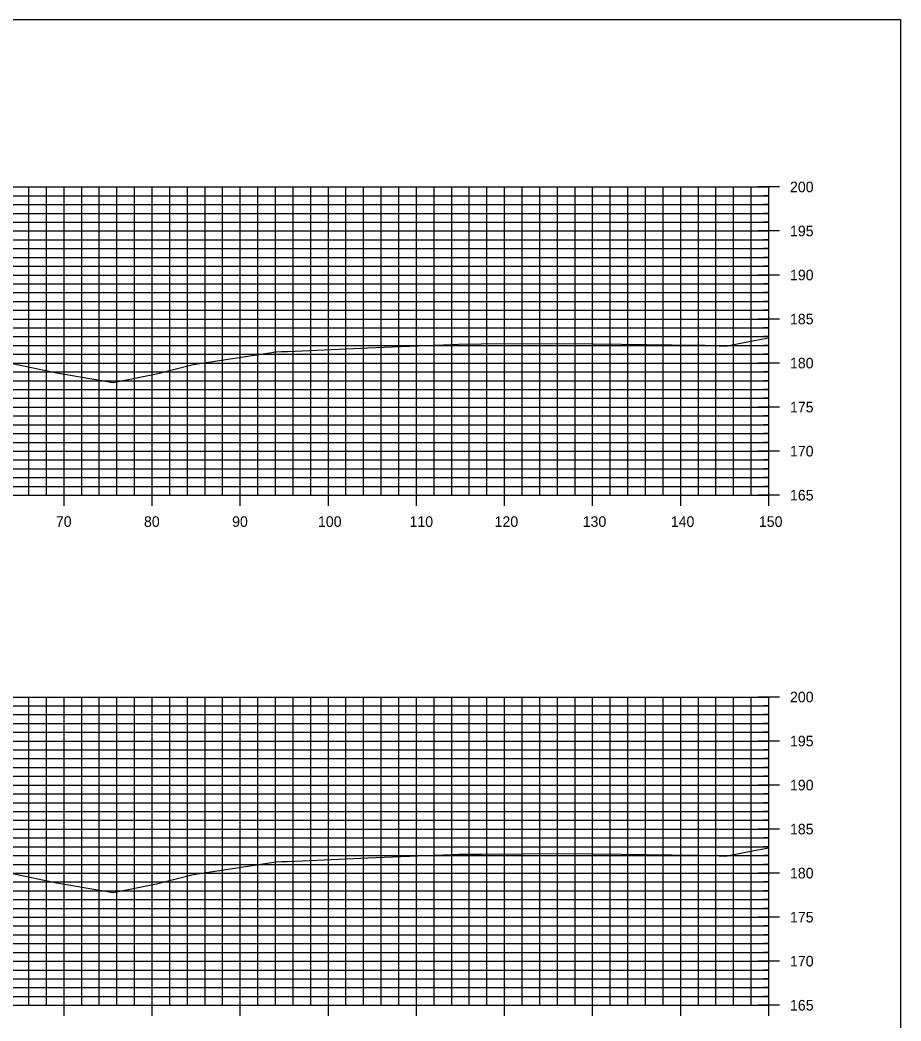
# Model space of a CAD drawing. Extents: x 1405440 to 1409538, y 1842123 to 1843178.
# Drawn here: x 1408947.6 to 1409047.6, y 1842829.8 to 1842943.5 of the extents above; entities that cross this region are included whole.
import ezdxf

# ---------------------------------------------------------------- set-up
doc = ezdxf.new("R2010")
doc.units = 0
for name, color, linetype in [('R_Axis Annot', 7, 'Continuous'), ('R_Exist Surface', 7, 'Continuous'), ('R_Grid_Minor', 7, 'Continuous'), ('R_Grid_Tick', 7, 'Continuous')]:
    doc.layers.add(name, color=color, linetype=linetype)

msp = doc.modelspace()

# ---------------------------------------------------------------- linework, layer by layer
for p, q in [((1408732.62, 1842924.51), (1409032.62, 1842924.51)), ((1408952.62, 1842889.51), (1408952.62, 1842924.51)), ((1408962.62, 1842889.51), (1408962.62, 1842924.51)), ((1408972.62, 1842889.51), (1408972.62, 1842924.51)), ((1408982.62, 1842889.51), (1408982.62, 1842924.51)), ((1408992.62, 1842889.51), (1408992.62, 1842924.51)), ((1409002.62, 1842889.51), (1409002.62, 1842924.51)), ((1409012.62, 1842889.51), (1409012.62, 1842924.51)), ((1409022.62, 1842889.51), (1409022.62, 1842924.51)), ((1409032.62, 1842889.51), (1409032.62, 1842924.51)), ((1409032.62, 1842889.51), (1409032.62, 1842924.51)), ((1408732.62, 1842919.51), (1409032.62, 1842919.51)), ((1408732.62, 1842914.51), (1409032.62, 1842914.51)), ((1408732.62, 1842909.51), (1409032.62, 1842909.51)), ((1408732.62, 1842904.51), (1409032.62, 1842904.51)), ((1408732.62, 1842899.51), (1409032.62, 1842899.51)), ((1408732.62, 1842894.51), (1409032.62, 1842894.51)), ((1408732.62, 1842889.51), (1409032.62, 1842889.51)), ((1408732.62, 1842889.51), (1409032.62, 1842889.51)), ((1408732.62, 1842866.59), (1409032.62, 1842866.59)), ((1408952.62, 1842831.59), (1408952.62, 1842866.59)), ((1408962.62, 1842831.59), (1408962.62, 1842866.59)), ((1408972.62, 1842831.59), (1408972.62, 1842866.59)), ((1408982.62, 1842831.59), (1408982.62, 1842866.59)), ((1408992.62, 1842831.59), (1408992.62, 1842866.59)), ((1409002.62, 1842831.59), (1409002.62, 1842866.59)), ((1409012.62, 1842831.59), (1409012.62, 1842866.59)), ((1409022.62, 1842831.59), (1409022.62, 1842866.59)), ((1409032.62, 1842831.59), (1409032.62, 1842866.59)), ((1409032.62, 1842831.59), (1409032.62, 1842866.59)), ((1408732.62, 1842861.59), (1409032.62, 1842861.59)), ((1408732.62, 1842856.59), (1409032.62, 1842856.59)), ((1408732.62, 1842851.59), (1409032.62, 1842851.59)), ((1408732.62, 1842846.59), (1409032.62, 1842846.59)), ((1408732.62, 1842841.59), (1409032.62, 1842841.59)), ((1408732.62, 1842836.59), (1409032.62, 1842836.59)), ((1408732.62, 1842831.59), (1409032.62, 1842831.59)), ((1408732.62, 1842831.59), (1409032.62, 1842831.59))]:
    msp.add_line(p, q)
msp.add_lwpolyline([(1408707.62, 1842723.47), (1409047.62, 1842723.47), (1409047.62, 1842943.47), (1408707.62, 1842943.47)], close=True)
at = {"layer": 'R_Exist Surface'}
for points in [[(1408942.42, 1842905.36), (1408951.8, 1842903.41), (1408958.19, 1842902.3), (1408963.11, 1842903.28), (1408967.28, 1842904.36), (1408976.7, 1842905.8), (1408977.29, 1842905.82), (1408977.99, 1842905.83), (1408987.09, 1842906.24), (1408989.9, 1842906.36), (1408996.59, 1842906.63), (1408997.4, 1842906.66), (1409000.02, 1842906.68), (1409009.47, 1842906.74), (1409015.89, 1842906.66), (1409021.63, 1842906.58), (1409022.6, 1842906.56), (1409024.57, 1842906.57), (1409026.22, 1842906.5), (1409027.7, 1842906.42), (1409030.97, 1842907.08), (1409032.62, 1842907.38)], [(1408942.42, 1842847.44), (1408951.8, 1842845.5), (1408958.19, 1842844.38), (1408963.11, 1842845.37), (1408967.28, 1842846.44), (1408976.7, 1842847.89), (1408977.29, 1842847.9), (1408977.99, 1842847.92), (1408987.09, 1842848.32), (1408989.9, 1842848.44), (1408996.59, 1842848.71), (1408997.4, 1842848.74), (1409000.02, 1842848.76), (1409009.47, 1842848.82), (1409015.89, 1842848.74), (1409021.63, 1842848.66), (1409022.6, 1842848.64), (1409024.57, 1842848.65), (1409026.22, 1842848.58), (1409027.7, 1842848.51), (1409030.97, 1842849.16), (1409032.62, 1842849.46)]]:
    msp.add_lwpolyline(points, dxfattribs=at)
at = {"layer": 'R_Grid_Minor'}
for p, q in [((1408948.62, 1842889.51), (1408948.62, 1842924.51)), ((1408950.62, 1842889.51), (1408950.62, 1842924.51)), ((1408954.62, 1842889.51), (1408954.62, 1842924.51)), ((1408956.62, 1842889.51), (1408956.62, 1842924.51)), ((1408958.62, 1842889.51), (1408958.62, 1842924.51)), ((1408960.62, 1842889.51), (1408960.62, 1842924.51)), ((1408964.62, 1842889.51), (1408964.62, 1842924.51)), ((1408966.62, 1842889.51), (1408966.62, 1842924.51)), ((1408968.62, 1842889.51), (1408968.62, 1842924.51)), ((1408970.62, 1842889.51), (1408970.62, 1842924.51)), ((1408974.62, 1842889.51), (1408974.62, 1842924.51)), ((1408976.62, 1842889.51), (1408976.62, 1842924.51)), ((1408978.62, 1842889.51), (1408978.62, 1842924.51)), ((1408980.62, 1842889.51), (1408980.62, 1842924.51)), ((1408984.62, 1842889.51), (1408984.62, 1842924.51)), ((1408986.62, 1842889.51), (1408986.62, 1842924.51)), ((1408988.62, 1842889.51), (1408988.62, 1842924.51)), ((1408990.62, 1842889.51), (1408990.62, 1842924.51)), ((1408994.62, 1842889.51), (1408994.62, 1842924.51)), ((1408996.62, 1842889.51), (1408996.62, 1842924.51)), ((1408998.62, 1842889.51), (1408998.62, 1842924.51)), ((1409000.62, 1842889.51), (1409000.62, 1842924.51)), ((1409004.62, 1842889.51), (1409004.62, 1842924.51)), ((1409006.62, 1842889.51), (1409006.62, 1842924.51)), ((1409008.62, 1842889.51), (1409008.62, 1842924.51)), ((1409010.62, 1842889.51), (1409010.62, 1842924.51)), ((1409014.62, 1842889.51), (1409014.62, 1842924.51)), ((1409016.62, 1842889.51), (1409016.62, 1842924.51)), ((1409018.62, 1842889.51), (1409018.62, 1842924.51)), ((1409020.62, 1842889.51), (1409020.62, 1842924.51)), ((1409024.62, 1842889.51), (1409024.62, 1842924.51)), ((1409026.62, 1842889.51), (1409026.62, 1842924.51)), ((1409028.62, 1842889.51), (1409028.62, 1842924.51)), ((1409030.62, 1842889.51), (1409030.62, 1842924.51)), ((1408732.62, 1842923.51), (1409032.62, 1842923.51)), ((1408732.62, 1842922.51), (1409032.62, 1842922.51)), ((1408732.62, 1842921.51), (1409032.62, 1842921.51)), ((1408732.62, 1842920.51), (1409032.62, 1842920.51)), ((1408732.62, 1842918.51), (1409032.62, 1842918.51)), ((1408732.62, 1842917.51), (1409032.62, 1842917.51)), ((1408732.62, 1842916.51), (1409032.62, 1842916.51)), ((1408732.62, 1842915.51), (1409032.62, 1842915.51)), ((1408732.62, 1842913.51), (1409032.62, 1842913.51)), ((1408732.62, 1842912.51), (1409032.62, 1842912.51)), ((1408732.62, 1842911.51), (1409032.62, 1842911.51)), ((1408732.62, 1842910.51), (1409032.62, 1842910.51)), ((1408732.62, 1842908.51), (1409032.62, 1842908.51)), ((1408732.62, 1842907.51), (1409032.62, 1842907.51)), ((1408732.62, 1842906.51), (1409032.62, 1842906.51)), ((1408732.62, 1842905.51), (1409032.62, 1842905.51)), ((1408732.62, 1842903.51), (1409032.62, 1842903.51)), ((1408732.62, 1842902.51), (1409032.62, 1842902.51)), ((1408732.62, 1842901.51), (1409032.62, 1842901.51)), ((1408732.62, 1842900.51), (1409032.62, 1842900.51)), ((1408732.62, 1842898.51), (1409032.62, 1842898.51)), ((1408732.62, 1842897.51), (1409032.62, 1842897.51)), ((1408732.62, 1842896.51), (1409032.62, 1842896.51)), ((1408732.62, 1842895.51), (1409032.62, 1842895.51)), ((1408732.62, 1842893.51), (1409032.62, 1842893.51)), ((1408732.62, 1842892.51), (1409032.62, 1842892.51)), ((1408732.62, 1842891.51), (1409032.62, 1842891.51)), ((1408732.62, 1842890.51), (1409032.62, 1842890.51)), ((1408948.62, 1842831.59), (1408948.62, 1842866.59)), ((1408950.62, 1842831.59), (1408950.62, 1842866.59)), ((1408954.62, 1842831.59), (1408954.62, 1842866.59)), ((1408956.62, 1842831.59), (1408956.62, 1842866.59)), ((1408958.62, 1842831.59), (1408958.62, 1842866.59)), ((1408960.62, 1842831.59), (1408960.62, 1842866.59)), ((1408964.62, 1842831.59), (1408964.62, 1842866.59)), ((1408966.62, 1842831.59), (1408966.62, 1842866.59)), ((1408968.62, 1842831.59), (1408968.62, 1842866.59)), ((1408970.62, 1842831.59), (1408970.62, 1842866.59)), ((1408974.62, 1842831.59), (1408974.62, 1842866.59)), ((1408976.62, 1842831.59), (1408976.62, 1842866.59)), ((1408978.62, 1842831.59), (1408978.62, 1842866.59)), ((1408980.62, 1842831.59), (1408980.62, 1842866.59)), ((1408984.62, 1842831.59), (1408984.62, 1842866.59)), ((1408986.62, 1842831.59), (1408986.62, 1842866.59)), ((1408988.62, 1842831.59), (1408988.62, 1842866.59)), ((1408990.62, 1842831.59), (1408990.62, 1842866.59)), ((1408994.62, 1842831.59), (1408994.62, 1842866.59)), ((1408996.62, 1842831.59), (1408996.62, 1842866.59)), ((1408998.62, 1842831.59), (1408998.62, 1842866.59)), ((1409000.62, 1842831.59), (1409000.62, 1842866.59)), ((1409004.62, 1842831.59), (1409004.62, 1842866.59)), ((1409006.62, 1842831.59), (1409006.62, 1842866.59)), ((1409008.62, 1842831.59), (1409008.62, 1842866.59)), ((1409010.62, 1842831.59), (1409010.62, 1842866.59)), ((1409014.62, 1842831.59), (1409014.62, 1842866.59)), ((1409016.62, 1842831.59), (1409016.62, 1842866.59)), ((1409018.62, 1842831.59), (1409018.62, 1842866.59)), ((1409020.62, 1842831.59), (1409020.62, 1842866.59)), ((1409024.62, 1842831.59), (1409024.62, 1842866.59)), ((1409026.62, 1842831.59), (1409026.62, 1842866.59)), ((1409028.62, 1842831.59), (1409028.62, 1842866.59)), ((1409030.62, 1842831.59), (1409030.62, 1842866.59)), ((1408732.62, 1842865.59), (1409032.62, 1842865.59)), ((1408732.62, 1842864.59), (1409032.62, 1842864.59)), ((1408732.62, 1842863.59), (1409032.62, 1842863.59)), ((1408732.62, 1842862.59), (1409032.62, 1842862.59)), ((1408732.62, 1842860.59), (1409032.62, 1842860.59)), ((1408732.62, 1842859.59), (1409032.62, 1842859.59)), ((1408732.62, 1842858.59), (1409032.62, 1842858.59)), ((1408732.62, 1842857.59), (1409032.62, 1842857.59)), ((1408732.62, 1842855.59), (1409032.62, 1842855.59)), ((1408732.62, 1842854.59), (1409032.62, 1842854.59)), ((1408732.62, 1842853.59), (1409032.62, 1842853.59)), ((1408732.62, 1842852.59), (1409032.62, 1842852.59)), ((1408732.62, 1842850.59), (1409032.62, 1842850.59)), ((1408732.62, 1842849.59), (1409032.62, 1842849.59)), ((1408732.62, 1842848.59), (1409032.62, 1842848.59)), ((1408732.62, 1842847.59), (1409032.62, 1842847.59)), ((1408732.62, 1842845.59), (1409032.62, 1842845.59)), ((1408732.62, 1842844.59), (1409032.62, 1842844.59)), ((1408732.62, 1842843.59), (1409032.62, 1842843.59)), ((1408732.62, 1842842.59), (1409032.62, 1842842.59)), ((1408732.62, 1842840.59), (1409032.62, 1842840.59)), ((1408732.62, 1842839.59), (1409032.62, 1842839.59)), ((1408732.62, 1842838.59), (1409032.62, 1842838.59)), ((1408732.62, 1842837.59), (1409032.62, 1842837.59)), ((1408732.62, 1842835.59), (1409032.62, 1842835.59)), ((1408732.62, 1842834.59), (1409032.62, 1842834.59)), ((1408732.62, 1842833.59), (1409032.62, 1842833.59)), ((1408732.62, 1842832.59), (1409032.62, 1842832.59))]:
    msp.add_line(p, q, dxfattribs=at)
at = {"layer": 'R_Grid_Tick'}
for p, q in [((1409033.82, 1842924.51), (1409031.42, 1842924.51)), ((1409032.62, 1842923.51), (1409032.02, 1842923.51)), ((1409032.62, 1842922.51), (1409032.02, 1842922.51)), ((1409032.62, 1842921.51), (1409032.02, 1842921.51)), ((1409032.62, 1842920.51), (1409032.02, 1842920.51)), ((1409033.82, 1842919.51), (1409031.42, 1842919.51)), ((1409032.62, 1842918.51), (1409032.02, 1842918.51)), ((1409032.62, 1842917.51), (1409032.02, 1842917.51)), ((1409032.62, 1842916.51), (1409032.02, 1842916.51)), ((1409032.62, 1842915.51), (1409032.02, 1842915.51)), ((1409033.82, 1842914.51), (1409031.42, 1842914.51)), ((1409032.62, 1842913.51), (1409032.02, 1842913.51)), ((1409032.62, 1842912.51), (1409032.02, 1842912.51)), ((1409032.62, 1842911.51), (1409032.02, 1842911.51)), ((1409032.62, 1842910.51), (1409032.02, 1842910.51)), ((1409033.82, 1842909.51), (1409031.42, 1842909.51)), ((1409032.62, 1842908.51), (1409032.02, 1842908.51)), ((1409032.62, 1842907.51), (1409032.02, 1842907.51)), ((1409032.62, 1842906.51), (1409032.02, 1842906.51)), ((1409033.82, 1842904.51), (1409031.42, 1842904.51)), ((1409032.62, 1842905.51), (1409032.02, 1842905.51)), ((1409032.62, 1842903.51), (1409032.02, 1842903.51)), ((1409032.62, 1842902.51), (1409032.02, 1842902.51)), ((1409032.62, 1842901.51), (1409032.02, 1842901.51)), ((1409032.62, 1842900.51), (1409032.02, 1842900.51)), ((1409033.82, 1842899.51), (1409031.42, 1842899.51)), ((1409032.62, 1842898.51), (1409032.02, 1842898.51)), ((1409032.62, 1842897.51), (1409032.02, 1842897.51)), ((1409032.62, 1842896.51), (1409032.02, 1842896.51)), ((1409032.62, 1842895.51), (1409032.02, 1842895.51)), ((1409033.82, 1842894.51), (1409031.42, 1842894.51)), ((1409032.62, 1842893.51), (1409032.02, 1842893.51)), ((1409032.62, 1842892.51), (1409032.02, 1842892.51)), ((1409032.62, 1842891.51), (1409032.02, 1842891.51)), ((1408948.62, 1842889.51), (1408948.62, 1842890.11)), ((1408950.62, 1842889.51), (1408950.62, 1842890.11)), ((1408952.62, 1842888.31), (1408952.62, 1842890.71)), ((1408954.62, 1842889.51), (1408954.62, 1842890.11)), ((1408956.62, 1842889.51), (1408956.62, 1842890.11)), ((1408958.62, 1842889.51), (1408958.62, 1842890.11)), ((1408960.62, 1842889.51), (1408960.62, 1842890.11)), ((1408962.62, 1842888.31), (1408962.62, 1842890.71)), ((1408964.62, 1842889.51), (1408964.62, 1842890.11)), ((1408966.62, 1842889.51), (1408966.62, 1842890.11)), ((1408968.62, 1842889.51), (1408968.62, 1842890.11)), ((1408970.62, 1842889.51), (1408970.62, 1842890.11)), ((1408972.62, 1842888.31), (1408972.62, 1842890.71)), ((1408974.62, 1842889.51), (1408974.62, 1842890.11)), ((1408976.62, 1842889.51), (1408976.62, 1842890.11)), ((1408978.62, 1842889.51), (1408978.62, 1842890.11)), ((1408980.62, 1842889.51), (1408980.62, 1842890.11)), ((1408982.62, 1842888.31), (1408982.62, 1842890.71)), ((1408984.62, 1842889.51), (1408984.62, 1842890.11)), ((1408986.62, 1842889.51), (1408986.62, 1842890.11)), ((1408988.62, 1842889.51), (1408988.62, 1842890.11)), ((1408990.62, 1842889.51), (1408990.62, 1842890.11)), ((1408992.62, 1842888.31), (1408992.62, 1842890.71)), ((1408994.62, 1842889.51), (1408994.62, 1842890.11)), ((1408996.62, 1842889.51), (1408996.62, 1842890.11)), ((1408998.62, 1842889.51), (1408998.62, 1842890.11)), ((1409000.62, 1842889.51), (1409000.62, 1842890.11)), ((1409002.62, 1842888.31), (1409002.62, 1842890.71)), ((1409004.62, 1842889.51), (1409004.62, 1842890.11)), ((1409006.62, 1842889.51), (1409006.62, 1842890.11)), ((1409008.62, 1842889.51), (1409008.62, 1842890.11)), ((1409010.62, 1842889.51), (1409010.62, 1842890.11)), ((1409012.62, 1842888.31), (1409012.62, 1842890.71)), ((1409014.62, 1842889.51), (1409014.62, 1842890.11)), ((1409016.62, 1842889.51), (1409016.62, 1842890.11)), ((1409018.62, 1842889.51), (1409018.62, 1842890.11)), ((1409020.62, 1842889.51), (1409020.62, 1842890.11)), ((1409022.62, 1842888.31), (1409022.62, 1842890.71)), ((1409024.62, 1842889.51), (1409024.62, 1842890.11)), ((1409026.62, 1842889.51), (1409026.62, 1842890.11)), ((1409028.62, 1842889.51), (1409028.62, 1842890.11)), ((1409030.62, 1842889.51), (1409030.62, 1842890.11)), ((1409032.62, 1842890.51), (1409032.02, 1842890.51)), ((1409032.62, 1842888.31), (1409032.62, 1842890.71)), ((1409033.82, 1842889.51), (1409031.42, 1842889.51)), ((1409033.82, 1842866.59), (1409031.42, 1842866.59)), ((1409032.62, 1842865.59), (1409032.02, 1842865.59)), ((1409032.62, 1842864.59), (1409032.02, 1842864.59)), ((1409032.62, 1842863.59), (1409032.02, 1842863.59)), ((1409032.62, 1842862.59), (1409032.02, 1842862.59)), ((1409033.82, 1842861.59), (1409031.42, 1842861.59)), ((1409032.62, 1842860.59), (1409032.02, 1842860.59)), ((1409032.62, 1842859.59), (1409032.02, 1842859.59)), ((1409032.62, 1842858.59), (1409032.02, 1842858.59)), ((1409032.62, 1842857.59), (1409032.02, 1842857.59)), ((1409033.82, 1842856.59), (1409031.42, 1842856.59)), ((1409032.62, 1842855.59), (1409032.02, 1842855.59)), ((1409032.62, 1842854.59), (1409032.02, 1842854.59)), ((1409032.62, 1842853.59), (1409032.02, 1842853.59)), ((1409032.62, 1842852.59), (1409032.02, 1842852.59)), ((1409033.82, 1842851.59), (1409031.42, 1842851.59)), ((1409032.62, 1842850.59), (1409032.02, 1842850.59)), ((1409032.62, 1842849.59), (1409032.02, 1842849.59)), ((1409032.62, 1842848.59), (1409032.02, 1842848.59)), ((1409033.82, 1842846.59), (1409031.42, 1842846.59)), ((1409032.62, 1842847.59), (1409032.02, 1842847.59)), ((1409032.62, 1842845.59), (1409032.02, 1842845.59)), ((1409032.62, 1842844.59), (1409032.02, 1842844.59)), ((1409032.62, 1842843.59), (1409032.02, 1842843.59)), ((1409032.62, 1842842.59), (1409032.02, 1842842.59)), ((1409033.82, 1842841.59), (1409031.42, 1842841.59)), ((1409032.62, 1842840.59), (1409032.02, 1842840.59)), ((1409032.62, 1842839.59), (1409032.02, 1842839.59)), ((1409032.62, 1842838.59), (1409032.02, 1842838.59)), ((1409032.62, 1842837.59), (1409032.02, 1842837.59)), ((1409033.82, 1842836.59), (1409031.42, 1842836.59)), ((1409032.62, 1842835.59), (1409032.02, 1842835.59)), ((1409032.62, 1842834.59), (1409032.02, 1842834.59)), ((1409032.62, 1842833.59), (1409032.02, 1842833.59)), ((1408948.62, 1842831.59), (1408948.62, 1842832.19)), ((1408950.62, 1842831.59), (1408950.62, 1842832.19)), ((1408952.62, 1842830.39), (1408952.62, 1842832.79)), ((1408954.62, 1842831.59), (1408954.62, 1842832.19)), ((1408956.62, 1842831.59), (1408956.62, 1842832.19)), ((1408958.62, 1842831.59), (1408958.62, 1842832.19)), ((1408960.62, 1842831.59), (1408960.62, 1842832.19)), ((1408962.62, 1842830.39), (1408962.62, 1842832.79)), ((1408964.62, 1842831.59), (1408964.62, 1842832.19)), ((1408966.62, 1842831.59), (1408966.62, 1842832.19)), ((1408968.62, 1842831.59), (1408968.62, 1842832.19)), ((1408970.62, 1842831.59), (1408970.62, 1842832.19)), ((1408972.62, 1842830.39), (1408972.62, 1842832.79)), ((1408974.62, 1842831.59), (1408974.62, 1842832.19)), ((1408976.62, 1842831.59), (1408976.62, 1842832.19)), ((1408978.62, 1842831.59), (1408978.62, 1842832.19)), ((1408980.62, 1842831.59), (1408980.62, 1842832.19)), ((1408982.62, 1842830.39), (1408982.62, 1842832.79)), ((1408984.62, 1842831.59), (1408984.62, 1842832.19)), ((1408986.62, 1842831.59), (1408986.62, 1842832.19)), ((1408988.62, 1842831.59), (1408988.62, 1842832.19)), ((1408990.62, 1842831.59), (1408990.62, 1842832.19)), ((1408992.62, 1842830.39), (1408992.62, 1842832.79)), ((1408994.62, 1842831.59), (1408994.62, 1842832.19)), ((1408996.62, 1842831.59), (1408996.62, 1842832.19)), ((1408998.62, 1842831.59), (1408998.62, 1842832.19)), ((1409000.62, 1842831.59), (1409000.62, 1842832.19)), ((1409002.62, 1842830.39), (1409002.62, 1842832.79)), ((1409004.62, 1842831.59), (1409004.62, 1842832.19)), ((1409006.62, 1842831.59), (1409006.62, 1842832.19)), ((1409008.62, 1842831.59), (1409008.62, 1842832.19)), ((1409010.62, 1842831.59), (1409010.62, 1842832.19)), ((1409012.62, 1842830.39), (1409012.62, 1842832.79)), ((1409014.62, 1842831.59), (1409014.62, 1842832.19)), ((1409016.62, 1842831.59), (1409016.62, 1842832.19)), ((1409018.62, 1842831.59), (1409018.62, 1842832.19)), ((1409020.62, 1842831.59), (1409020.62, 1842832.19)), ((1409022.62, 1842830.39), (1409022.62, 1842832.79)), ((1409024.62, 1842831.59), (1409024.62, 1842832.19)), ((1409026.62, 1842831.59), (1409026.62, 1842832.19)), ((1409028.62, 1842831.59), (1409028.62, 1842832.19)), ((1409030.62, 1842831.59), (1409030.62, 1842832.19)), ((1409032.62, 1842832.59), (1409032.02, 1842832.59)), ((1409032.62, 1842830.39), (1409032.62, 1842832.79)), ((1409033.82, 1842831.59), (1409031.42, 1842831.59))]:
    msp.add_line(p, q, dxfattribs=at)

# ---------------------------------------------------------------- texts
at = {"layer": 'R_Axis Annot'}
for s, p in [('200', (1409035.02, 1842923.91)), ('195', (1409035.02, 1842918.91)), ('190', (1409035.02, 1842913.91)), ('185', (1409035.02, 1842908.91)), ('180', (1409035.02, 1842903.91)), ('175', (1409035.02, 1842898.91)), ('170', (1409035.02, 1842893.91)), ('165', (1409035.02, 1842888.91)), ('70', (1408951.69, 1842885.91)), ('80', (1408961.69, 1842885.91)), ('90', (1408971.69, 1842885.91)), ('100', (1408981.44, 1842885.91)), ('110', (1408991.83, 1842885.91)), ('120', (1409001.49, 1842885.91)), ('130', (1409011.49, 1842885.91)), ('140', (1409021.49, 1842885.91)), ('150', (1409031.49, 1842885.91)), ('200', (1409035.02, 1842865.99)), ('195', (1409035.02, 1842860.99)), ('190', (1409035.02, 1842855.99)), ('185', (1409035.02, 1842850.99)), ('180', (1409035.02, 1842845.99)), ('175', (1409035.02, 1842840.99)), ('170', (1409035.02, 1842835.99)), ('165', (1409035.02, 1842830.99))]:
    msp.add_text(s, height=1.2, dxfattribs=at).set_placement(p)

doc.saveas('drawing.dxf')
